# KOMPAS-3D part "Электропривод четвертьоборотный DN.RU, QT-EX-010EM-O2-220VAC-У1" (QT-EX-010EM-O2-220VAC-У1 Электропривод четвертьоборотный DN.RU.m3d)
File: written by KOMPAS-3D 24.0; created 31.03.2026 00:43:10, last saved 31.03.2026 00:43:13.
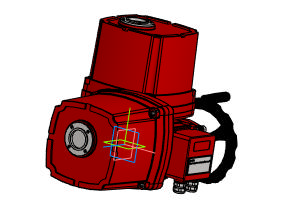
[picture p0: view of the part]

Document properties: Автор: DN.RU; Полное имя файла: D:\PROJECT CAD\DN.RU\...194\Исходники\QT-EX-010EM-O2-220VAC-У1\QT-EX-010EM-O2-220VAC-У1 Электропривод четвертьоборотный DN.RU.m3d

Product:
- Body: Твердое тело1  | qty 1
    Масса: 65.658095
- Part/product: Электропривод четвертьоборотный DN.RU  | designation QT-EX-010EM-O2-220VAC-У1
    Масса: 13
    Раздел спецификации: Прочие изделия
    Комментарий: D300-04899
    Примечание: D300-04899
    additional columns: Сталь

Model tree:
1. Твердое тело1  (labels: Твердое тело1)

Expressions: QT-EX-010EM-O2-220VAC-У1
